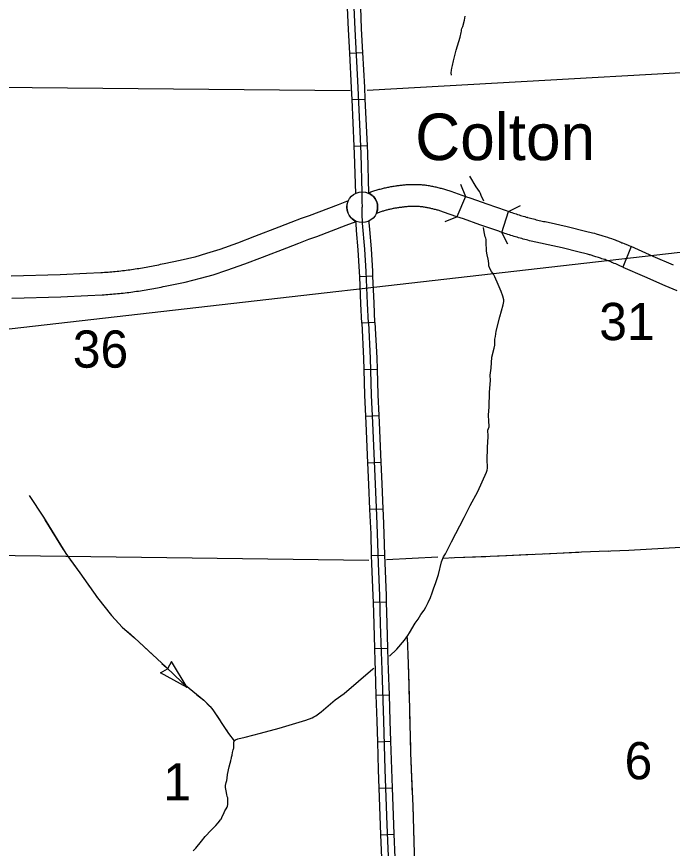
# Model space of a CAD drawing. Extents: x 1720274 to 1751788, y 372074 to 391887.
# Drawn here: x 1735303 to 1736478, y 376511 to 378002 of the extents above; entities that cross this region are included whole.
import ezdxf

# ---------------------------------------------------------------- set-up
doc = ezdxf.new("R2010")
doc.units = 0
for name, color, linetype in [('Level 10', 7, 'Continuous'), ('Level 24', 7, 'Continuous'), ('Level 32', 7, 'Continuous'), ('Level 35', 7, 'Continuous'), ('Level 37', 7, 'Continuous'), ('Level 4', 7, 'Continuous'), ('Level 43', 7, 'Continuous'), ('Level 5', 7, 'Continuous'), ('R_Draft', 7, 'Continuous')]:
    doc.layers.add(name, color=color, linetype=linetype)

msp = doc.modelspace()

# ---------------------------------------------------------------- linework, layer by layer
at = {"layer": 'Level 10'}
for p, q in [((1736107.1, 377679.6), (1736091.5, 377643.3)), ((1736172, 377615.2), (1736184.2, 377652.8)), ((1736218.3, 377641.9), (1736218.2, 377642)), ((1736207.7, 377603.9), (1736207.6, 377603.9)), ((1736403.6, 377589.7), (1736388.7, 377553)), ((1736403.6, 377589.7), (1736388.7, 377553))]:
    msp.add_line(p, q, dxfattribs=at)
for points in [[(1735932.5, 377685.8), (1735933.6, 377686.2), (1735935.4, 377686.9), (1735937.3, 377687.6), (1735939.1, 377688.2), (1735941, 377688.9), (1735942.9, 377689.5), (1735944.7, 377690.1), (1735946.6, 377690.7), (1735948.5, 377691.3), (1735950.4, 377691.8), (1735952.3, 377692.4), (1735954.2, 377692.9), (1735956.1, 377693.4), (1735958, 377693.9), (1735959.9, 377694.3), (1735961.8, 377694.8), (1735963.7, 377695.2), (1735965.7, 377695.7), (1735967.6, 377696.1), (1735969.5, 377696.4), (1735971.4, 377696.8), (1735973.4, 377697.2), (1735975.3, 377697.5), (1735977.3, 377697.8), (1735979.2, 377698.1), (1735981.2, 377698.4), (1735983.1, 377698.7), (1735984.7, 377698.9), (1735986.1, 377699.1), (1735987.8, 377699.4), (1735989.6, 377699.6), (1735991.4, 377699.8), (1735993.2, 377700), (1735995, 377700.2), (1735996.8, 377700.4), (1735998.6, 377700.6), (1736000.5, 377700.7), (1736002.3, 377700.9), (1736004.1, 377701), (1736005.9, 377701.1), (1736007.7, 377701.1), (1736009.5, 377701.2), (1736011.3, 377701.2), (1736013.1, 377701.2), (1736014.9, 377701.2), (1736016.8, 377701.2), (1736018.6, 377701.2), (1736020.4, 377701.1), (1736022.2, 377701.1), (1736024, 377701), (1736025.8, 377700.9), (1736027.6, 377700.8), (1736029.4, 377700.6), (1736031.6, 377700.4), (1736033.9, 377700.1), (1736035.9, 377699.8), (1736037.9, 377699.5), (1736039.9, 377699.2), (1736041.8, 377698.9), (1736043.8, 377698.5), (1736045.8, 377698.2), (1736047.7, 377697.8), (1736049.7, 377697.4), (1736051.7, 377697), (1736053.6, 377696.6), (1736055.6, 377696.1), (1736057.5, 377695.6), (1736059.5, 377695.2), (1736061.4, 377694.7), (1736063.4, 377694.2), (1736065.3, 377693.6), (1736067.2, 377693.1), (1736069.1, 377692.5), (1736071.1, 377691.9), (1736073, 377691.3), (1736074.9, 377690.7), (1736076.8, 377690.1), (1736078.7, 377689.4), (1736080.5, 377688.8), (1736107.1, 377679.6)], [(1735896.7, 377671.7), (1735878.7, 377664.7), (1735826.6, 377645)], [(1736107.1, 377679.6), (1736116.3, 377676.5), (1736145.4, 377666.2), (1736179.8, 377654.3), (1736182.5, 377653.4), (1736184.2, 377652.8)], [(1736091.5, 377643.3), (1736067.5, 377651.5), (1736065.8, 377652.1), (1736064.2, 377652.6), (1736062.7, 377653.2), (1736061.1, 377653.7), (1736059.5, 377654.2), (1736057.9, 377654.7), (1736056.3, 377655.1), (1736054.7, 377655.6), (1736053.1, 377656), (1736051.4, 377656.4), (1736049.8, 377656.9), (1736048.2, 377657.3), (1736046.6, 377657.6), (1736045, 377658), (1736043.3, 377658.4), (1736041.7, 377658.7), (1736040.1, 377659.1), (1736038.4, 377659.4), (1736036.8, 377659.7), (1736035.1, 377660), (1736033.5, 377660.2), (1736031.9, 377660.5), (1736030.2, 377660.7), (1736028.6, 377661), (1736027.2, 377661.1), (1736026.2, 377661.2), (1736024.7, 377661.4), (1736023.3, 377661.5), (1736021.9, 377661.5), (1736020.5, 377661.6), (1736019.1, 377661.7), (1736017.6, 377661.7), (1736016.2, 377661.7), (1736014.8, 377661.7), (1736013.4, 377661.7), (1736011.9, 377661.7), (1736010.5, 377661.7), (1736009.1, 377661.7), (1736007.7, 377661.6), (1736006.2, 377661.5), (1736004.8, 377661.4), (1736003.4, 377661.3), (1736002, 377661.2), (1736000.6, 377661.1), (1735999.1, 377661), (1735997.7, 377660.8), (1735996.3, 377660.6), (1735994.9, 377660.5), (1735993.5, 377660.3), (1735992.1, 377660), (1735990.3, 377659.8), (1735988.3, 377659.5), (1735986.7, 377659.3), (1735985.1, 377659.1), (1735983.5, 377658.8), (1735981.9, 377658.5), (1735980.3, 377658.3), (1735978.7, 377658), (1735977.1, 377657.7), (1735975.5, 377657.4), (1735973.9, 377657), (1735972.3, 377656.7), (1735970.8, 377656.3), (1735969.2, 377656), (1735967.6, 377655.6), (1735966, 377655.2), (1735964.5, 377654.7), (1735962.9, 377654.3), (1735961.4, 377653.9), (1735959.8, 377653.4), (1735958.3, 377652.9), (1735956.7, 377652.5), (1735955.2, 377652), (1735953.6, 377651.5), (1735952.1, 377650.9), (1735950.6, 377650.4), (1735949.1, 377649.8), (1735947.2, 377649.1)], [(1736184.2, 377652.8), (1736185.1, 377652.4), (1736187.6, 377651.6), (1736190.1, 377650.7), (1736192.6, 377649.8), (1736195.2, 377649), (1736197.7, 377648.1), (1736200.3, 377647.3), (1736202.8, 377646.5), (1736205.4, 377645.7), (1736207.9, 377644.9), (1736210.5, 377644.2), (1736213.1, 377643.4), (1736215.6, 377642.7), (1736218.3, 377641.9)], [(1735826.6, 377645), (1735812.4, 377639.9), (1735793.8, 377632.6), (1735772.7, 377624.4), (1735728.8, 377607.7), (1735698.1, 377595.9), (1735666.7, 377584.7), (1735643.1, 377577.1), (1735622.1, 377571), (1735595.9, 377564.7), (1735566.7, 377558.7), (1735563.3, 377558), (1735560.1, 377557.3), (1735556.9, 377556.6), (1735553.7, 377555.9), (1735550.5, 377555.3), (1735547.3, 377554.6), (1735544.1, 377554), (1735540.9, 377553.4), (1735537.7, 377552.8), (1735534.5, 377552.2), (1735531.3, 377551.6), (1735528, 377551.1), (1735524.8, 377550.6), (1735521.6, 377550), (1735518.4, 377549.5), (1735515.1, 377549.1), (1735511.9, 377548.6), (1735508.7, 377548.1), (1735505.4, 377547.7), (1735502.2, 377547.2), (1735499, 377546.8), (1735495.7, 377546.4), (1735492.5, 377546), (1735489.2, 377545.7), (1735486, 377545.3), (1735482.7, 377545), (1735479.5, 377544.7), (1735476.2, 377544.4), (1735473, 377544.1), (1735469.7, 377543.8), (1735466.5, 377543.5), (1735463.2, 377543.3), (1735460, 377543), (1735456.7, 377542.8), (1735453.5, 377542.6), (1735427.9, 377541.2), (1735380.4, 377538.9), (1735293.1, 377536.8)], [(1736172, 377615.2), (1736169.1, 377616.2), (1736166.6, 377617.1), (1736132.4, 377628.9), (1736103.3, 377639.2), (1736091.5, 377643.3)], [(1736218.2, 377642), (1736220.8, 377641.3), (1736223.4, 377640.6), (1736226, 377639.9), (1736228.6, 377639.2), (1736231.2, 377638.6), (1736233.8, 377637.9), (1736236.4, 377637.3), (1736239, 377636.7), (1736241.6, 377636.1), (1736244.2, 377635.5), (1736246.8, 377634.9), (1736249.4, 377634.4), (1736252, 377633.9), (1736254.9, 377633.3), (1736289, 377625.7), (1736324.3, 377616.9)], [(1735840.3, 377608), (1735892.8, 377627.8), (1735911, 377634.9)], [(1735294.3, 377497.3), (1735381.9, 377499.4), (1735430, 377501.8), (1735455.8, 377503.2), (1735459.3, 377503.4), (1735462.7, 377503.6), (1735466.1, 377503.9), (1735469.6, 377504.1), (1735473, 377504.4), (1735476.5, 377504.7), (1735479.9, 377505), (1735483.3, 377505.3), (1735486.8, 377505.7), (1735490.2, 377506), (1735493.6, 377506.4), (1735497, 377506.8), (1735500.5, 377507.2), (1735503.9, 377507.6), (1735507.3, 377508.1), (1735510.7, 377508.5), (1735514.1, 377509), (1735517.6, 377509.5), (1735521, 377510), (1735524.4, 377510.5), (1735527.8, 377511), (1735531.2, 377511.6), (1735534.6, 377512.1), (1735538, 377512.7), (1735541.4, 377513.3), (1735544.8, 377513.9), (1735548.2, 377514.6), (1735551.6, 377515.2), (1735555, 377515.9), (1735558.3, 377516.5), (1735561.7, 377517.2), (1735565.1, 377517.9), (1735568.5, 377518.6), (1735571.8, 377519.4), (1735575, 377520.1), (1735604.5, 377526.1), (1735632.2, 377532.8), (1735654.6, 377539.3), (1735679.3, 377547.2), (1735711.8, 377558.8), (1735743, 377570.8), (1735786.9, 377587.6), (1735808.2, 377595.8), (1735826.3, 377602.9), (1735840.3, 377608)], [(1736207.6, 377603.9), (1736204.9, 377604.7), (1736202.1, 377605.5), (1736199.3, 377606.3), (1736196.5, 377607.1), (1736193.8, 377608), (1736191, 377608.8), (1736188.3, 377609.7), (1736185.5, 377610.6), (1736182.8, 377611.5), (1736180, 377612.4), (1736177.3, 377613.3), (1736174.6, 377614.3), (1736172, 377615.2)], [(1736324.3, 377616.9), (1736332.3, 377614.9), (1736334.2, 377614.5), (1736338.3, 377613.5), (1736340.9, 377612.8), (1736350.9, 377609.7), (1736352.8, 377609.1), (1736357, 377607.8), (1736361.2, 377606.3), (1736362.7, 377605.9), (1736364.3, 377605.4), (1736368.5, 377604.2), (1736371.3, 377603.2), (1736373.3, 377602.4), (1736375.3, 377601.6), (1736377.3, 377600.8), (1736379.3, 377600), (1736381.3, 377599.2), (1736383.3, 377598.3), (1736385.3, 377597.4), (1736387.1, 377596.6), (1736388.1, 377596.2), (1736390.9, 377595.2), (1736398.2, 377592), (1736403.6, 377589.7)], [(1736310.4, 377579.6), (1736279.9, 377587.3), (1736246.8, 377594.6), (1736244.2, 377595.1), (1736241.4, 377595.7), (1736238.5, 377596.3), (1736235.7, 377596.9), (1736232.9, 377597.6), (1736230.1, 377598.2), (1736227.3, 377598.9), (1736224.4, 377599.5), (1736221.6, 377600.2), (1736218.8, 377600.9), (1736216, 377601.7), (1736213.2, 377602.4), (1736210.4, 377603.1), (1736207.7, 377603.9)], [(1736388.7, 377553), (1736382.5, 377555.8), (1736376.3, 377558.5), (1736373.4, 377559.5), (1736371.1, 377560.5), (1736369.2, 377561.3), (1736367.5, 377562.1), (1736365.8, 377562.8), (1736364.1, 377563.5), (1736362.4, 377564.3), (1736360.7, 377564.9), (1736359, 377565.6), (1736357.2, 377566.3), (1736356.2, 377566.7), (1736353.7, 377567.4), (1736351.4, 377568), (1736348.9, 377568.8), (1736344.9, 377570.2), (1736340.6, 377571.5), (1736338.7, 377572.1), (1736330.2, 377574.8), (1736329, 377575.1), (1736325.3, 377576), (1736323.2, 377576.4), (1736310.4, 377579.6)], [(1736479.7, 377556.4), (1736443.4, 377572.2), (1736403.6, 377589.7)], [(1736388.7, 377553), (1736427.6, 377536), (1736464.1, 377520.2), (1736485.6, 377511)]]:
    msp.add_lwpolyline(points, dxfattribs=at)
for start, end in [(336.1547, 67.3234), (155.6819, 246.8511)]:
    msp.add_arc((1735921.9, 377660.3), 27.6, start, end, dxfattribs=at)
at = {"layer": 'Level 24'}
msp.add_circle((1735921.9, 377660.3), 27.6, dxfattribs=at)
at = {"layer": 'Level 32'}
for p, q in [((1735898.8, 377936.3), (1735922.5, 377937.6)), ((1735903.1, 377853.1), (1735926.8, 377854.2)), ((1735906.8, 377769.8), (1735930.5, 377770.8)), ((1735941, 377536.5), (1735917.3, 377535.6)), ((1735944.7, 377453.3), (1735921.1, 377452.1)), ((1735924.8, 377369.1), (1735948.5, 377369.7)), ((1735928, 377285.4), (1735951.7, 377286.6)), ((1735931.6, 377202.2), (1735955.3, 377203.2)), ((1735935, 377118.8), (1735958.7, 377119.8)), ((1735938.1, 377035.7), (1735961.7, 377036.2)), ((1735941.2, 376952.2), (1735964.9, 376953)), ((1735943.7, 376868.9), (1735967.4, 376869.5)), ((1735946.4, 376785.5), (1735970.1, 376786.2)), ((1735949.1, 376702.1), (1735972.8, 376702.8)), ((1735951.8, 376618.7), (1735975.5, 376619.5)), ((1735954.8, 376535.2), (1735978.5, 376536.2))]:
    msp.add_line(p, q, dxfattribs=at)
for points in [[(1735882.4, 378520.2), (1735882.6, 378499.2), (1735887.6, 378402.8), (1735892.2, 378304.8), (1735893.9, 378271.2), (1735897.3, 378202.9), (1735899.1, 378147.3), (1735903.5, 378092.1), (1735906.8, 378018.3), (1735908.4, 377979.6), (1735914, 377874.6), (1735919.3, 377756.2), (1735921.4, 377686.8), (1735921.4, 377671.3), (1735921.9, 377660.3)], [(1735894.9, 378019.8), (1735895, 378017.8), (1735896.5, 377979.1), (1735898.8, 377936.3)], [(1735918.6, 378020.8), (1735918.6, 378018.9), (1735920.2, 377980.2), (1735922.5, 377937.6)], [(1735898.8, 377936.3), (1735902.2, 377874), (1735903.1, 377853.1)], [(1735922.5, 377937.6), (1735925.9, 377875.2), (1735926.8, 377854.2)], [(1735903.1, 377853.1), (1735906.8, 377769.8)], [(1735926.8, 377854.2), (1735930.5, 377770.8)], [(1735930.5, 377770.8), (1735931.1, 377756.6), (1735933.3, 377686.1)], [(1735906.8, 377769.8), (1735907.4, 377755.7), (1735909.6, 377685.1)], [(1735932.9, 377452.7), (1735931.1, 377487.8), (1735928.8, 377545.1), (1735926.3, 377584.8), (1735922.6, 377631.7), (1735921.5, 377648.8), (1735921.9, 377660.3)], [(1735911.8, 377618.4), (1735910.8, 377630.9), (1735910.6, 377635.1)], [(1735935.4, 377620.2), (1735934.5, 377632.6), (1735934.3, 377635.6)], [(1735917.3, 377535.6), (1735916.9, 377544.5), (1735914.5, 377584), (1735911.8, 377618.4)], [(1735941, 377536.5), (1735940.6, 377545.7), (1735938.2, 377585.6), (1735935.4, 377620.2)], [(1735921.1, 377452.1), (1735919.3, 377487.3), (1735917.3, 377535.6)], [(1735944.7, 377453.3), (1735943, 377488.4), (1735941, 377536.5)], [(1735921.1, 377452.1), (1735924.3, 377389.1), (1735924.8, 377369.1)], [(1735932.9, 377452.7), (1735936.1, 377389.6), (1735937.9, 377323.6), (1735940.5, 377273.8), (1735945, 377163.6), (1735947.4, 377107.4), (1735948.9, 377075.1), (1735950.2, 377022.2), (1735952.7, 376963.8), (1735954.2, 376913.3), (1735956.2, 376846.7), (1735956.8, 376830.9), (1735959.7, 376739.2), (1735962.5, 376652.3), (1735966, 376553), (1735970.6, 376439.9)], [(1735944.7, 377453.3), (1735948, 377390.1), (1735948.5, 377369.7)], [(1735924.8, 377369.1), (1735926.1, 377323.1), (1735928, 377285.4)], [(1735948.5, 377369.7), (1735949.8, 377324), (1735951.7, 377286.6)], [(1735928, 377285.4), (1735928.6, 377273.2), (1735931.6, 377202.2)], [(1735951.7, 377286.6), (1735952.3, 377274.3), (1735955.3, 377203.2)], [(1735931.6, 377202.2), (1735933.2, 377163.1), (1735935, 377118.8)], [(1735955.3, 377203.2), (1735956.9, 377164.1), (1735958.7, 377119.8)], [(1735935, 377118.8), (1735935.5, 377106.9), (1735937.1, 377074.6), (1735938.1, 377035.7)], [(1735958.7, 377119.8), (1735959.2, 377107.9), (1735960.8, 377075.5), (1735961.7, 377036.2)], [(1735938.1, 377035.7), (1735938.4, 377021.8), (1735940.9, 376963.4), (1735941.2, 376952.2)], [(1735961.7, 377036.2), (1735962.1, 377022.6), (1735964.6, 376964.2), (1735964.9, 376953)], [(1735941.2, 376952.2), (1735942.4, 376913), (1735943.7, 376868.9)], [(1735964.9, 376953), (1735966.1, 376913.7), (1735967.4, 376869.5)], [(1735943.7, 376868.9), (1735944.3, 376846.3), (1735945, 376830.4), (1735946.4, 376785.5)], [(1735967.4, 376869.5), (1735968, 376847.1), (1735968.6, 376831.3), (1735970.1, 376786.2)], [(1735946.4, 376785.5), (1735947.9, 376738.8), (1735949.1, 376702.1)], [(1735970.1, 376786.2), (1735971.6, 376739.6), (1735972.8, 376702.8)], [(1735949.1, 376702.1), (1735950.7, 376651.9), (1735951.8, 376618.7)], [(1735972.8, 376702.8), (1735974.4, 376652.7), (1735975.5, 376619.5)], [(1735951.8, 376618.7), (1735954.1, 376552.5), (1735954.8, 376535.2)], [(1735975.5, 376619.5), (1735977.8, 376553.4), (1735978.5, 376536.2)], [(1735954.8, 376535.2), (1735958.3, 376451.9)], [(1735978.5, 376536.2), (1735981.9, 376452.8)]]:
    msp.add_lwpolyline(points, dxfattribs=at)
at = {"layer": 'Level 35'}
for points in [[(1736081.8, 377896.8), (1736081.5, 377900.9), (1736081.7, 377905.7), (1736082.2, 377909.6), (1736083.8, 377914.1), (1736085.6, 377922.4), (1736090.2, 377941.7), (1736097.2, 377965.2), (1736099.4, 377973.7), (1736099.6, 377976), (1736100, 377978.2), (1736100.5, 377980.7), (1736102.2, 377984.5), (1736105, 377995.4), (1736106.3, 378002.7)], [(1736135.6, 377679.3), (1736133.5, 377685.1), (1736132, 377688.3), (1736126.3, 377696.8), (1736114.8, 377715.8)], [(1736140, 377671.1), (1736139.3, 377672.8), (1736135.6, 377679.3)], [(1735970.9, 376855.7), (1735983.8, 376868), (1735997.8, 376883.9), (1736003.5, 376892.2), (1736006.6, 376897.2), (1736017, 376914.5), (1736021.8, 376921.8), (1736026.8, 376929.9), (1736032.7, 376937.7), (1736036, 376943), (1736040.3, 376951.5), (1736044.1, 376960.3), (1736047.4, 376969.1), (1736049.7, 376975.9), (1736053.5, 376987.3), (1736058.5, 377001.8), (1736064, 377024.3), (1736067.5, 377033.6), (1736071.1, 377039.1), (1736081.7, 377060.4), (1736104.7, 377104.1), (1736115.4, 377125.7), (1736129.2, 377150.6), (1736144.3, 377185), (1736145.8, 377188.8), (1736146.2, 377192.6), (1736146.5, 377196.1), (1736145.8, 377205.4), (1736146.2, 377230.3), (1736147.7, 377248.8), (1736147.7, 377252.8), (1736146.7, 377257.3), (1736146.9, 377260.4), (1736148.4, 377263.5), (1736149.1, 377266.8), (1736149.1, 377268.5), (1736148.6, 377275.9), (1736148.4, 377288.2), (1736149.5, 377302), (1736149.8, 377328.5), (1736151.4, 377349.4), (1736151, 377359.1), (1736152.6, 377371.7), (1736154.1, 377391.2), (1736158.1, 377407.8), (1736159.7, 377412.8), (1736159.7, 377415.6), (1736159.3, 377418.7), (1736159.5, 377423.9), (1736160.5, 377428.2), (1736162.1, 377437.9), (1736168.5, 377464), (1736174.2, 377485.4), (1736175.4, 377491.5), (1736175.4, 377494.4), (1736173.7, 377500.8), (1736170.9, 377509.1), (1736165.7, 377521.7), (1736159.7, 377535.4), (1736156.9, 377540.4), (1736153.3, 377544.9), (1736150.3, 377550.4), (1736148.6, 377554.9), (1736148.7, 377559), (1736148.4, 377563.9), (1736147.8, 377567.4), (1736145.9, 377574.9), (1736144.7, 377581.5), (1736144, 377598), (1736143.8, 377602.4), (1736143.5, 377604.6), (1736142.4, 377607.3), (1736140.5, 377616.4), (1736139.4, 377623.9)], [(1736362.3, 377043.8), (1736367.4, 377044), (1736399.6, 377045.3), (1736492.9, 377051.1), (1736536.6, 377052.6), (1736643, 377058.3), (1736687.1, 377060.4), (1736718.6, 377064), (1736741.9, 377068.8), (1736777.9, 377078.7), (1736815.1, 377088.1), (1736838.4, 377094), (1736843, 377095.4)], [(1735693.3, 376704.5), (1735694.6, 376705.4), (1735699.1, 376707.5), (1735711.9, 376710.5), (1735739.7, 376717.3), (1735773.3, 376726.3), (1735820.7, 376740.6), (1735832.4, 376744.6), (1735835.4, 376746.5), (1735838.8, 376748.4), (1735848.2, 376755.7), (1735873.1, 376776.9), (1735889.5, 376788.5), (1735940.9, 376832.6), (1735942.4, 376833.8)], [(1735618.9, 376506.4), (1735623.5, 376511.2), (1735633.7, 376524), (1735640.6, 376532), (1735651, 376543.7), (1735659.3, 376551.9), (1735663.5, 376556.8), (1735668.1, 376561.9), (1735669, 376563.4), (1735670.6, 376566.2), (1735674.5, 376575.4), (1735675.8, 376577.9), (1735678.3, 376581.8), (1735679.7, 376584.7), (1735680.2, 376586.8), (1735680.9, 376589.6), (1735681.1, 376592), (1735681.1, 376597), (1735681.1, 376599.3), (1735680.8, 376601.5), (1735679.7, 376604.1), (1735679.1, 376607.2), (1735677.9, 376614), (1735677, 376620), (1735677, 376622.5), (1735677.1, 376624.5), (1735677.6, 376626.1), (1735678.3, 376628.8), (1735679.1, 376632.6), (1735679.8, 376637), (1735680.6, 376643.4), (1735683.4, 376656.8), (1735685.5, 376663.9), (1735686.2, 376667.8), (1735686.8, 376671.2), (1735687.6, 376672.6), (1735687.9, 376674.1), (1735688.7, 376677.7), (1735689.2, 376682.5), (1735689.8, 376685.4), (1735690.5, 376687.5), (1735691.5, 376689.4), (1735691.9, 376690.3), (1735692.1, 376692.4), (1735692, 376701.9), (1735692.3, 376702.7), (1735692.7, 376703.7), (1735693.3, 376704.5)]]:
    msp.add_lwpolyline(points, dxfattribs=at)
at = {"layer": 'Level 37'}
for points in [[(1736098.2, 377701.6), (1736107.1, 377679.6)], [(1736184.2, 377652.8), (1736205.3, 377663.5)], [(1736091.8, 377643.2), (1736069.8, 377634.3)], [(1736182.7, 377594.1), (1736172, 377615.2)]]:
    msp.add_lwpolyline(points, dxfattribs=at)
at = {"layer": 'Level 4'}
for points in [[(1734964.1, 377039.7), (1735118.3, 377038.3), (1735933.7, 377027.7)], [(1735965.5, 377028.7), (1736057.2, 377033.4)]]:
    msp.add_lwpolyline(points, dxfattribs=at)
at = {"layer": 'Level 43'}
for p, q in [((1735560.7, 376825.3), (1735573.1, 376832.8)), ((1735580.1, 376845.6), (1735573.2, 376832.9)), ((1735608.3, 376799.3), (1735580.1, 376845.6)), ((1735608.3, 376799.3), (1735560.7, 376825.3))]:
    msp.add_line(p, q, dxfattribs=at)
for points in [[(1735325.4, 377143.6), (1735350.5, 377104.4), (1735390.6, 377039.5), (1735416, 377004.9), (1735447.3, 376960), (1735472.6, 376928.1), (1735491.7, 376907.6), (1735513.8, 376888.2), (1735570.4, 376835.5), (1735598.4, 376808.8), (1735611.5, 376797.9), (1735638.2, 376776.5), (1735649.4, 376764.9), (1735654.4, 376759), (1735682.3, 376716.8), (1735692.7, 376703.7)], [(1735353.4, 377099.6), (1735386.3, 377046.4)], [(1736362.3, 377043.8), (1736314.6, 377041.7), (1736270.8, 377039.6), (1736167.4, 377034.5), (1736087.3, 377031.6), (1736066.1, 377030.8)], [(1736310.2, 377041.5), (1736270.8, 377039.6), (1736247.7, 377038.5)], [(1736362.3, 377043.8), (1736331.1, 377042.4)], [(1735398.1, 377029.2), (1735416, 377004.9), (1735434.5, 376978.3)], [(1736143.6, 377033.7), (1736087.3, 377031.6), (1736081, 377031.4)], [(1736226.9, 377037.4), (1736167.4, 377034.5), (1736164.4, 377034.4)], [(1735446.4, 376961.2), (1735447.3, 376960), (1735472.6, 376928.1), (1735486.5, 376913.2)], [(1735501.6, 376898.9), (1735513.8, 376888.2), (1735547.7, 376856.6)], [(1736002.4, 376888.7), (1736003.7, 376857.7), (1736004.6, 376824.7), (1736006.4, 376761.1), (1736008.4, 376682), (1736009.3, 376652.5), (1736012.3, 376587.3), (1736014.3, 376523), (1736015.7, 376482.2), (1736016.4, 376450.4), (1736018, 376408.6), (1736021.7, 376321)], [(1736002.4, 376888.7), (1736003.7, 376857.7), (1736003.7, 376857.5)], [(1735563, 376842.4), (1735570.4, 376835.5), (1735598.4, 376808.8), (1735609, 376800)], [(1736004.2, 376836.6), (1736004.6, 376824.7), (1736006, 376774.1)], [(1735625.2, 376786.9), (1735638.2, 376776.5), (1735648.4, 376766)], [(1735648.4, 376766), (1735649.4, 376764.9), (1735654.4, 376759), (1735666.6, 376740.6)], [(1736006.6, 376753.2), (1736008.2, 376690.7)], [(1735678.1, 376723.2), (1735682.3, 376716.8), (1735692.7, 376703.7)], [(1736008.8, 376669.8), (1736009.3, 376652.5), (1736011.4, 376607.3)], [(1736012.3, 376586.5), (1736014.3, 376524)]]:
    msp.add_lwpolyline(points, dxfattribs=at)
at = {"layer": 'Level 5'}
for points in [[(1735930.6, 377870.3), (1736800.8, 377919.3)], [(1735076.5, 377877.1), (1735900.4, 377869.2)]]:
    msp.add_lwpolyline(points, dxfattribs=at)
at = {"layer": 'R_Draft'}
msp.add_line((1737452.7, 377689.1), (1728670.7, 376684.2), dxfattribs=at)

# ---------------------------------------------------------------- texts
at = {"layer": 'Level 24'}
msp.add_text('Colton', height=83.42, dxfattribs=at).set_placement((1736016.8, 377744.7))
at = {"layer": 'Level 5'}
for s, height, p in [('31', 66.74, (1736346.5, 377422)), ('36', 66.74, (1735403.3, 377372.6)), ('6', 66.7, (1736391.9, 376634.7)), ('1', 66.7, (1735565.4, 376596.8))]:
    msp.add_text(s, height=height, dxfattribs=at).set_placement(p)

doc.saveas('drawing.dxf')
